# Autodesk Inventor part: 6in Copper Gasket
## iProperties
Shininess: 64.0
Length Units: 11272
Angle Units: 11279
Time Units: 11290
Mass Units: 11286
Length Display Precision: 3
Angle Display Precision: 2
Compacted: True
Part Number: 6in Copper Gasket
Document SubType Name: Modeling
Created: 2003-08
Designer: FT User
Manufacturer: Standard
Standards Organization: Custom
Density: 0.0
Volumn: 0.0
Area: 0.0
PropertySet Name: Model Information
Control State: 0
Master: False
Checked Out: False
Author: FT User
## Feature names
1. Extrusion1
